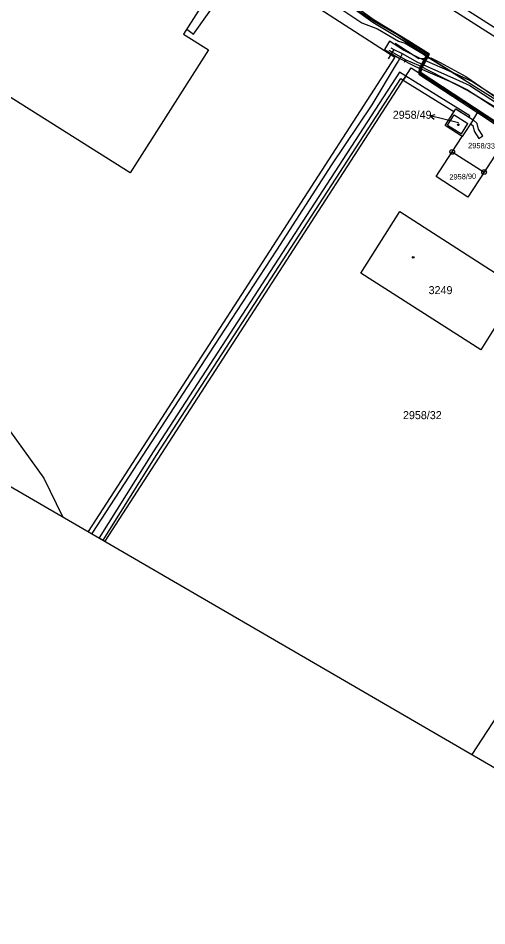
# Model space of a CAD drawing. Extents: x -621168 to -620292, y -1122748 to -1122069.
# Drawn here: x -620861.7 to -620762.3, y -1122596.3 to -1122403.6 of the extents above; entities that cross this region are included whole.
import ezdxf

# ---------------------------------------------------------------- set-up
doc = ezdxf.new("R2010")
doc.units = 0
for name, color, linetype in [('CETIN', 7, 'Continuous'), ('GasNet', 7, 'Continuous'), ('Hranice parcel', 7, 'Continuous'), ('itself', 7, 'Continuous'), ('Parcelní čísla', 7, 'Continuous'), ('Pop  PČ popisy', 7, 'Continuous'), ('Rámečky-tisk', 7, 'Continuous'), ('VAS stoka', 7, 'Continuous'), ('VAS vodovod', 7, 'Continuous'), ('Vnitřní kresba', 7, 'Continuous'), ('Věcná břemena k části', 7, 'Continuous'), ('Značky bodu BP', 7, 'Continuous'), ('Značky budov', 7, 'Continuous')]:
    doc.layers.add(name, color=color, linetype=linetype)

msp = doc.modelspace()

# ---------------------------------------------------------------- linework, layer by layer
at = {"layer": 'CETIN'}
for points in [[(-620825.92, -1122405.87), (-620824.51, -1122406.99), (-620818.94, -1122399.06), (-620813.77, -1122391.56), (-620811.94, -1122388.94), (-620806.05, -1122392.88), (-620797.93, -1122398.39), (-620788.82, -1122404.57), (-620785.51, -1122405.86), (-620781.04, -1122408.44), (-620779.59, -1122408.85), (-620776.1, -1122410.97), (-620774.86, -1122411.81), (-620766.93, -1122416.76), (-620729.54, -1122440.11), (-620722.4, -1122445), (-620713.88, -1122450.37)], [(-620776.1, -1122410.97), (-620779.59, -1122408.85)], [(-620766.93, -1122416.76), (-620774.86, -1122411.81)]]:
    msp.add_lwpolyline(points, dxfattribs=at)
at = {"layer": 'GasNet'}
for points in [[(-620780.25, -1122411.07), (-620780.49, -1122411.62), (-620780.55, -1122411.72), (-620781.12, -1122412.67), (-620781.53, -1122413.35), (-620786.71, -1122421.95), (-620795.26, -1122434.7), (-620806.92, -1122452.79), (-620820.16, -1122473.03), (-620834.32, -1122494.96), (-620846.08, -1122513)], [(-620782.01, -1122410.24), (-620783.22, -1122412.2)], [(-620782.63, -1122409.86), (-620782.01, -1122410.24), (-620780.25, -1122411.07), (-620777.02, -1122412.94), (-620768.84, -1122416.49), (-620765.93, -1122417.88), (-620758.63, -1122422.59), (-620737.62, -1122436.24), (-620727.26, -1122442.97), (-620706.73, -1122456.7), (-620700.22, -1122460.96), (-620682.51, -1122472.52), (-620658.5, -1122488), (-620649.67, -1122493.31), (-620649.45, -1122493.45), (-620648.52, -1122494.04), (-620647.09, -1122494.92), (-620646.9, -1122495.04), (-620639.06, -1122500.54), (-620610.88, -1122519.2), (-620586.31, -1122535.34), (-620573.22, -1122543.96)]]:
    msp.add_lwpolyline(points, dxfattribs=at)
at = {"layer": 'Hranice parcel'}
for p, q in [((-620765.22, -1122425.14), (-620764.06, -1122423.34)), ((-620764.06, -1122423.34), (-620757.34, -1122427.68)), ((-620765.22, -1122425.14), (-620767.52, -1122428.7)), ((-620769.63, -1122431.96), (-620767.52, -1122428.7)), ((-620757.34, -1122427.68), (-620762.87, -1122436.24)), ((-620769.63, -1122431.96), (-620762.87, -1122436.24)), ((-620765.39, -1122559.92), (-620757.37, -1122547.51))]:
    msp.add_line(p, q, dxfattribs=at)
for points in [[(-620933.94, -1122313.6), (-620948.13, -1122341.18), (-620940.52, -1122363.74), (-620929.94, -1122378.34), (-620917.61, -1122395.34), (-620915.85, -1122441.34), (-620895.21, -1122457.01), (-620870.85, -1122481.07), (-620856.26, -1122501.24), (-620852.32, -1122509.38)], [(-620929.94, -1122378.34), (-620913.46, -1122352.29), (-620887.98, -1122368.3), (-620877.81, -1122374.71), (-620872.17, -1122365.51), (-620820.94, -1122397.9), (-620826.62, -1122407), (-620821.36, -1122410.31), (-620837.94, -1122436.41), (-620904.18, -1122394.6), (-620929.94, -1122378.34)], [(-620557.45, -1122536.96), (-620684.91, -1122455.63), (-620825.92, -1122365.89)], [(-620848.87, -1122368.55), (-620781.81, -1122411.87), (-620814.37, -1122462.27), (-620846.85, -1122512.55)], [(-620843.28, -1122514.63), (-620778.34, -1122414.11), (-620764.06, -1122423.34)], [(-620767.52, -1122428.7), (-620771.15, -1122426.36), (-620768.9, -1122422.81), (-620765.22, -1122425.14)], [(-620762.87, -1122436.24), (-620766.29, -1122441.54), (-620773.01, -1122437.2), (-620769.63, -1122431.96)], [(-620758.93, -1122466.63), (-620763.57, -1122474.01), (-620789, -1122457.71), (-620780.78, -1122444.6), (-620755.36, -1122460.94), (-620754.9, -1122461.23), (-620750.13, -1122453.84), (-620724.79, -1122470.34), (-620733.19, -1122483.27), (-620758.55, -1122466.88), (-620758.93, -1122466.63)]]:
    msp.add_lwpolyline(points, dxfattribs=at)
at = {"layer": 'itself'}
msp.add_lwpolyline([(-620745.77, -1122435.49), (-620776.46, -1122415.3), (-620776.4, -1122414.33), (-620775.69, -1122413.16), (-620774.76, -1122411.29), (-620776.99, -1122409.87), (-620778.95, -1122408.64), (-620781.22, -1122407.1), (-620786.31, -1122404.21), (-620793, -1122399.61)], dxfattribs=at)
at = {"layer": 'Pop  PČ popisy'}
for p, q in [((-620774.33, -1122424.27), (-620773.24, -1122424.03)), ((-620771.42, -1122425), (-620774.33, -1122424.27)), ((-620774.33, -1122424.27), (-620773.48, -1122425)), ((-620768.29, -1122425.79), (-620771.42, -1122425))]:
    msp.add_line(p, q, dxfattribs=at)
at = {"layer": 'Rámečky-tisk'}
msp.add_lwpolyline([(-621018.54, -1122069.17), (-621167.83, -1122325.92), (-620441.66, -1122748.16)], dxfattribs=at)
at = {"layer": 'VAS stoka'}
msp.add_lwpolyline([(-620781.72, -1122408.87), (-620776.69, -1122412.14), (-620774.2, -1122412.02), (-620772.21, -1122412.95), (-620766.77, -1122415.95), (-620758.11, -1122421.89), (-620737.16, -1122435.39), (-620726.71, -1122442.22), (-620705.9, -1122455.54), (-620681.71, -1122471.08), (-620665.23, -1122481.83), (-620655.61, -1122488.12), (-620638.12, -1122499.53), (-620609.99, -1122517.38), (-620585.88, -1122533.44), (-620564.23, -1122548.6), (-620546.83, -1122572.05), (-620541.25, -1122582.33), (-620541.87, -1122584.42), (-620543.53, -1122584.85), (-620544.25, -1122585.03)], dxfattribs=at)
at = {"layer": 'VAS vodovod'}
for points in [[(-620783.05, -1122410.36), (-620779.49, -1122412.44), (-620776.82, -1122413.57), (-620766.15, -1122419), (-620759.23, -1122423.16), (-620738.05, -1122436.88), (-620666.7, -1122483.31), (-620630.69, -1122506.76), (-620611.44, -1122519.95), (-620587.32, -1122536.52), (-620566.14, -1122551.51), (-620558.22, -1122559.71), (-620551.85, -1122569.08), (-620547.83, -1122576.32), (-620546.15, -1122586.98), (-620546.1, -1122587.26)], [(-620779.75, -1122412.92), (-620779.61, -1122412.64), (-620779.49, -1122412.44)]]:
    msp.add_lwpolyline(points, dxfattribs=at)
at = {"layer": 'Vnitřní kresba'}
for p, q in [((-620810.36, -1122373.73), (-620648.08, -1122477.56)), ((-620770.64, -1122426.28), (-620769.25, -1122424.08)), ((-620769.25, -1122424.08), (-620766.31, -1122425.96)), ((-620770.64, -1122426.28), (-620767.68, -1122428.15)), ((-620767.68, -1122428.15), (-620766.31, -1122425.96))]:
    msp.add_line(p, q, dxfattribs=at)
at = {"layer": 'Věcná břemena k části'}
msp.add_line((-620844.54, -1122513.9), (-620843.67, -1122514.41), dxfattribs=at)
for points in [[(-620794.95, -1122398.24), (-620786.45, -1122404.42), (-620779.08, -1122408.85), (-620775.09, -1122411.38), (-620776.65, -1122414.26), (-620776.7, -1122415.17), (-620748.87, -1122433.15), (-620776.2, -1122415.17), (-620776.15, -1122414.4), (-620774.43, -1122411.2), (-620778.82, -1122408.43), (-620786.17, -1122404), (-620794.67, -1122397.82)], [(-620758.09, -1122421.75), (-620765.44, -1122417.01), (-620768.43, -1122415.58), (-620776.6, -1122412.03), (-620779.94, -1122410.35), (-620782.95, -1122408.48), (-620784.01, -1122410.19), (-620780.92, -1122412.09), (-620777.44, -1122413.85), (-620769.25, -1122417.4), (-620766.42, -1122418.75), (-620759.17, -1122423.43)], [(-620843.67, -1122514.41), (-620832.28, -1122496.21), (-620780.51, -1122416.41), (-620780.02, -1122416.71), (-620779.48, -1122415.87), (-620780.82, -1122415.04), (-620833.1, -1122495.63), (-620844.54, -1122513.9)]]:
    msp.add_lwpolyline(points, dxfattribs=at)
for points in [[(-620721.8, -1122451.06), (-620717.36, -1122453.51), (-620741.38, -1122437.99), (-620745.63, -1122435.28), (-620748.87, -1122433.15), (-620776.7, -1122415.17), (-620776.72, -1122415.43), (-620764.25, -1122423.63), (-620757.57, -1122428.03), (-620745.91, -1122435.7)], [(-620779.48, -1122415.87), (-620780.02, -1122416.71), (-620769.26, -1122423.38), (-620768.9, -1122422.81), (-620768.58, -1122423.01), (-620766.07, -1122424.6), (-620765.88, -1122424.3)], [(-620765.22, -1122425.14), (-620765.76, -1122425.98), (-620765.28, -1122426.39), (-620765.01, -1122427.55), (-620763.99, -1122429.09), (-620763.16, -1122428.53), (-620764.07, -1122427.15), (-620764.36, -1122425.91)]]:
    msp.add_lwpolyline(points, close=True, dxfattribs=at)
at = {"layer": 'Značky bodu BP'}
for centre, radius in [((-620769.63, -1122431.96), 0.5), ((-620769.63, -1122431.96), 0.0303), ((-620762.87, -1122436.24), 0.5), ((-620762.87, -1122436.24), 0.0303)]:
    msp.add_circle(centre, radius, dxfattribs=at)
at = {"layer": 'Značky budov'}
for centre in [(-620768.32, -1122426.2), (-620777.91, -1122454.36)]:
    msp.add_circle(centre, 0.175, dxfattribs=at)

# ---------------------------------------------------------------- texts
at = {"layer": 'Parcelní čísla'}
for s, p in [('2958/49', (-620782.24, -1122424.93)), ('3249', (-620774.64, -1122462.16)), ('2958/32', (-620780.08, -1122488.7))]:
    msp.add_text(s, height=1.7, dxfattribs=at).set_placement(p)
for s, rotation, p in [('2958/33', 359, (-620766.26, -1122431.17)), ('2958/90', 2, (-620770.22, -1122437.87))]:
    msp.add_text(s, height=1.139, rotation=rotation, dxfattribs=at).set_placement(p)

doc.saveas('drawing.dxf')
